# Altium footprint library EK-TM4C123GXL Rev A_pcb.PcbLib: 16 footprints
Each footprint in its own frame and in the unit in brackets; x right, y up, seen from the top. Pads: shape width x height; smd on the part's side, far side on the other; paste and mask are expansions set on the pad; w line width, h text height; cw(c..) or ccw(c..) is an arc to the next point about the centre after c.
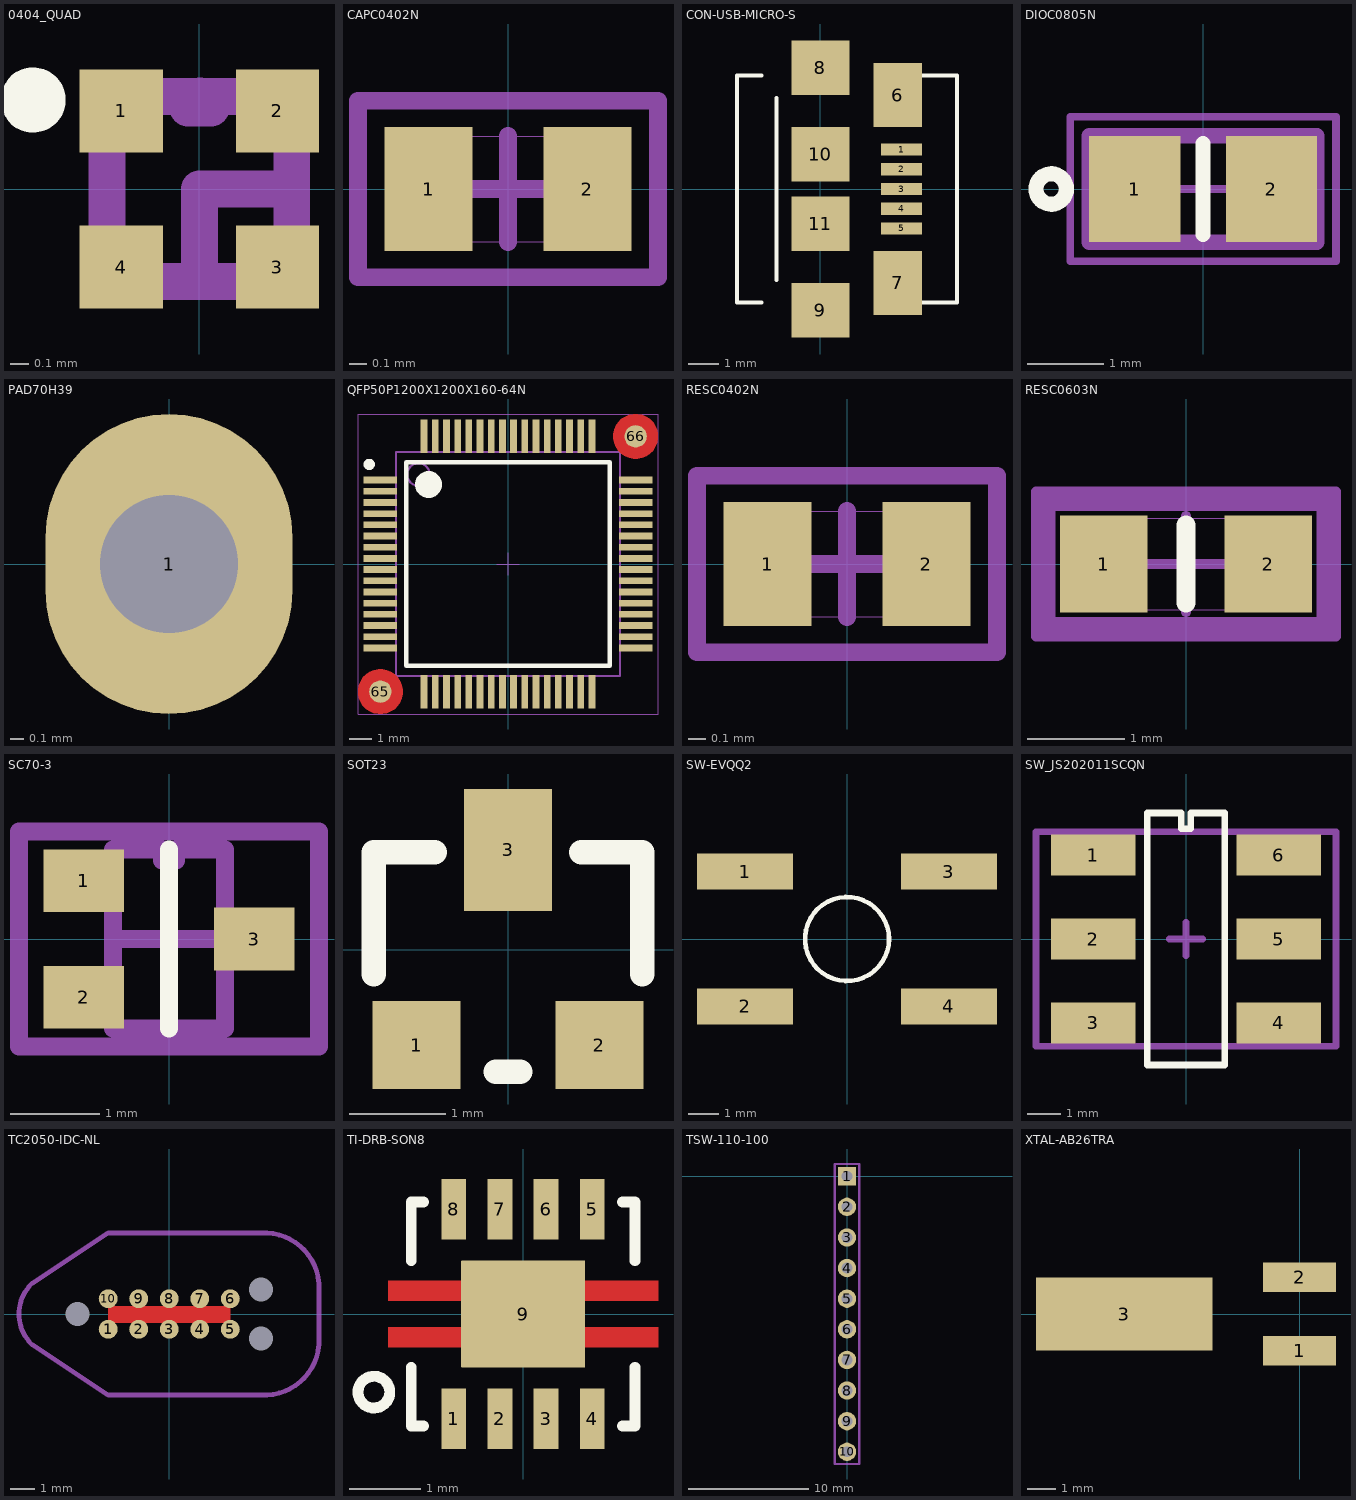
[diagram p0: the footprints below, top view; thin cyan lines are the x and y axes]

## 0404_QUAD [mm]
height 1
pads (4):
  rrect0% 0.45x0.45 smd: 1(-0.423,0.423) 2(0.423,0.423) 3(0.423,-0.423) 4(-0.423,-0.423)
Top Overlay:
  circle w0.2: c-0.9,0.482 r0.076
Mechanical 1:
  lines w0.2: -0.5,-0.5 0.5,-0.5 0.5,0.5 0.062,0.5 0.062,0.437 -0.062,0.437 0.004,0.504 -0.5,0.5 -0.5,-0.5
  text "D1" at 0.406,0.914 h0.64
Mechanical 16:
  lines w0.2: 0,-0.5 0,0 0.5,0 ; -0.5,-0.5 0.5,-0.5 0.5,0.5 -0.5,0.5 -0.5,-0.5

## CAPC0402N [mm]
pads (2):
  rect 0.5x0.7 smd: 1(-0.45,0) 2(0.45,0)
Mechanical 1:
  lines w0.1: -0.85,-0.5 0.85,-0.5 0.85,0.5 -0.85,0.5 -0.85,-0.5
  text "C1" at -0.219,-0.175 h0.38
Mechanical 16:
  lines w0.001: -0.55,-0.3 0.55,-0.3 0.55,0.3 -0.55,0.3 -0.55,-0.3
  lines w0.1: -0.3,0 0.3,0 ; 0,-0.3 0,0.3 ; -0.85,-0.5 0.85,-0.5 0.85,0.5 -0.85,0.5 -0.85,-0.5

## CON-USB-MICRO-S [mm]
pads (11):
  rect 1.35x0.4 smd: 1(2.675,1.3) 2(2.675,0.65) 3(2.675,0) 4(2.675,-0.65) 5(2.675,-1.3)
  rect 1.6x2.1 smd: 6(2.55,3.1) 7(2.55,-3.1)
  rect 1.9x1.8 smd: 8(0,4) 9(0,-4) 10(0,1.15) 11(0,-1.15)
Top Overlay:
  lines w0.127: -1.95,-3.75 -2.75,-3.75 -2.75,3.75 -1.95,3.75 ; -1.45,-3 -1.45,3 ; 2.5,-3.75 4.5,-3.75 4.5,3.75 2.5,3.75

## DIOC0805N [mm]
pads (2):
  rect 1.2x1.4 smd: 1(-0.9,0) 2(0.9,0)
Top Overlay:
  circle w0.2: c-2,0 r0.2
  lines w0.2: 0,-0.6 0,0.6
Mechanical 1:
  lines w0.2: -1.5,-0.7 1.5,-0.7 1.5,0.7 -1.5,0.7 -1.5,-0.7
  text "D4" at -0.456,-0.325 h0.6
Mechanical 16:
  lines w0.001: -1.075,-0.7 1.075,-0.7 1.075,0.7 -1.075,0.7 -1.075,-0.7
  lines w0.1: -0.5,0 0.5,0 ; 0,-0.5 0,0.5 ; -1.75,-0.95 1.75,-0.95 1.75,0.95 -1.75,0.95 -1.75,-0.95

## PAD70H39 [mil]
pads (1):
  oval 70x85 / inner round 70 / far side oval 70x85 hole 39: 1(0,0)

## QFP50P1200X1200X160-64N [mm]
height 1.6
pads (66):
  rect 1.5x0.3 smd: 1(-5.7,3.75) 2(-5.7,3.25) 3(-5.7,2.75) 4(-5.7,2.25) 5(-5.7,1.75) 6(-5.7,1.25) 7(-5.7,0.75) 8(-5.7,0.25) 9(-5.7,-0.25) 10(-5.7,-0.75) 11(-5.7,-1.25) 12(-5.7,-1.75) 13(-5.7,-2.25) 14(-5.7,-2.75) 15(-5.7,-3.25) 16(-5.7,-3.75) 33(5.7,-3.75) 34(5.7,-3.25) 35(5.7,-2.75) 36(5.7,-2.25) 37(5.7,-1.75) 38(5.7,-1.25) 39(5.7,-0.75) 40(5.7,-0.25) 41(5.7,0.25) 42(5.7,0.75) 43(5.7,1.25) 44(5.7,1.75) 45(5.7,2.25) 46(5.7,2.75) 47(5.7,3.25) 48(5.7,3.75)
  rect 0.3x1.5 smd: 17(-3.75,-5.7) 18(-3.25,-5.7) 19(-2.75,-5.7) 20(-2.25,-5.7) 21(-1.75,-5.7) 22(-1.25,-5.7) 23(-0.75,-5.7) 24(-0.25,-5.7) 25(0.25,-5.7) 26(0.75,-5.7) 27(1.25,-5.7) 28(1.75,-5.7) 29(2.25,-5.7) 30(2.75,-5.7) 31(3.25,-5.7) 32(3.75,-5.7) 49(3.75,5.7) 50(3.25,5.7) 51(2.75,5.7) 52(2.25,5.7) 53(1.75,5.7) 54(1.25,5.7) 55(0.75,5.7) 56(0.25,5.7) 57(-0.25,5.7) 58(-0.75,5.7) 59(-1.25,5.7) 60(-1.75,5.7) 61(-2.25,5.7) 62(-2.75,5.7) 63(-3.25,5.7) 64(-3.75,5.7)
  round 1 smd mask+0.5: 65(-5.7,-5.7) 66(5.7,5.7)
Top Layer:
  pour cut-out: -4.7,-5.7 -4.7,-5.602 -4.738,-5.408 -4.814,-5.226 -4.923,-5.063 -5.063,-4.923 -5.226,-4.814 -5.408,-4.738 -5.602,-4.7 -5.7,-4.7 -5.798,-4.7 -5.992,-4.738 -6.174,-4.814 -6.337,-4.923 -6.477,-5.063 -6.586,-5.226 -6.662,-5.408 -6.7,-5.602 -6.7,-5.7 -6.7,-5.798 -6.662,-5.992 -6.586,-6.174 -6.477,-6.337 -6.337,-6.477 -6.174,-6.586 -5.992,-6.662 -5.798,-6.7 -5.7,-6.7 -5.602,-6.7 -5.408,-6.662 -5.226,-6.586 -5.063,-6.477 -4.923,-6.337 -4.814,-6.174 -4.738,-5.992 -4.7,-5.798
  pour cut-out: 6.7,5.7 6.7,5.798 6.662,5.992 6.586,6.174 6.477,6.337 6.337,6.477 6.174,6.586 5.992,6.662 5.798,6.7 5.7,6.7 5.602,6.7 5.408,6.662 5.226,6.586 5.063,6.477 4.923,6.337 4.814,6.174 4.738,5.992 4.7,5.798 4.7,5.7 4.7,5.602 4.738,5.408 4.814,5.226 4.923,5.063 5.063,4.923 5.226,4.814 5.408,4.738 5.602,4.7 5.7,4.7 5.798,4.7 5.992,4.738 6.174,4.814 6.337,4.923 6.477,5.063 6.586,5.226 6.662,5.408 6.7,5.602
Top Overlay:
  circle w0.6: c-3.55,3.55 r0.3
  circle w0.25: c-6.2,4.45 r0.125
  lines w0.2: -4.55,-4.55 4.55,-4.55 4.55,4.55 -4.55,4.55 -4.55,-4.55
Mechanical 1:
  circle w0.1: c-4,4 r0.5
  lines w0.1: -5,-5 5,-5 5,5 -5,5 -5,-5
  text "U1" at -0.451,-0.394 h0.64
Mechanical 16:
  lines w0.001: -5,-5 5,-5 5,5 -5,5 -5,-5
  lines w0.05: -0.5,0 0.5,0 ; 0,-0.5 0,0.5 ; -6.7,-6.7 6.7,-6.7 6.7,6.7 -6.7,6.7 -6.7,-6.7

## RESC0402N [mm]
height 0.35
pads (2):
  rect 0.5x0.7 smd: 1(-0.45,0) 2(0.45,0)
Mechanical 1:
  lines w0.1: -0.85,-0.5 0.85,-0.5 0.85,0.5 -0.85,0.5 -0.85,-0.5
  text "R17" at -0.417,-0.175 h0.38
Mechanical 16:
  lines w0.001: -0.55,-0.3 0.55,-0.3 0.55,0.3 -0.55,0.3 -0.55,-0.3
  lines w0.1: -0.3,0 0.3,0 ; 0,-0.3 0,0.3 ; -0.85,-0.5 0.85,-0.5 0.85,0.5 -0.85,0.5 -0.85,-0.5

## RESC0603N [mm]
height 0.6
pads (2):
  rect 0.9x1 smd: 1(-0.85,0) 2(0.85,0)
Top Overlay:
  lines w0.2: 0,-0.4 0,0.4
Mechanical 1:
  lines w0.2: -1.45,-0.65 1.45,-0.65 1.45,0.65 -1.45,0.65 -1.45,-0.65
  text "R1" at -0.384,-0.344 h0.64
Mechanical 16:
  lines w0.001: -0.85,-0.475 0.85,-0.475 0.85,0.475 -0.85,0.475 -0.85,-0.475
  lines w0.1: -0.5,0 0.5,0 ; 0,-0.5 0,0.5 ; -1.55,-0.75 1.55,-0.75 1.55,0.75 -1.55,0.75 -1.55,-0.75

## SC70-3 [mm]
height 1.27
pads (3):
  rect 0.9x0.7 smd: 1(-0.95,0.65) 2(-0.95,-0.65) 3(0.95,0)
Top Overlay:
  lines w0.2: 0,1 0,0.875 0,1 ; 0,1 0,-1 0,1
Mechanical 1:
  lines w0.2: -0.625,-1 0.625,-1 0.625,1 0.078,1 0.078,0.875 -0.078,0.875 -0.078,1 -0.625,1 -0.625,-1
  text "D2" at 0,0 h0.44
Mechanical 16:
  lines w0.2: -0.5,0 0,0 ; 0,-0.5 0,0 ; 0,0.5 0,0 ; 0.5,0 0,0 ; -1.675,-1.2 1.675,-1.2 1.675,1.2 -1.675,1.2 -1.675,-1.2

## SOT23 [mil]
height 50
pads (3):
  rect 36x36 smd: 1(-37.5,-39) 2(37.5,-39)
  rect 36x50 smd: 3(0,41)
Top Overlay:
  lines w10: -55,-10 -55,40 -30,40 ; -5,-50 5,-50 ; 30,40 55,40 55,-10
Mechanical 1:
  text "Q1" at -67.78,-15.33 h25

## SW-EVQQ2 [mm]
pads (4):
  rect 3.2x1.2 smd: 1(-3.4,2.25) 2(-3.4,-2.25) 3(3.4,2.25) 4(3.4,-2.25)
Top Overlay:
  circle w0.152: c0,0 r1.4
Mechanical 1:
  text "RESET" at -1.575,-0.406 h0.64

## SW_JS202011SCQN [mil]
height 50
pads (6):
  rect 98.5x48 smd: 1(-108.25,98) 2(-108.25,0) 3(-108.25,-98) 4(108.25,-98) 5(108.25,0) 6(108.25,98)
Top Overlay:
  lines w7.87: -45.22,-147 45.22,-147 45.22,147 5.65,147 5.65,128.62 -5.65,128.62 -5.65,147 -45.22,147 -45.22,-147
Mechanical 16:
  lines w7.87: -19.68,0 0,0 ; 0,-19.68 0,0 ; 0,19.68 0,0 ; 19.68,0 0,0 ; -175,-125 175,-125 175,125 -175,125 -175,-125

## TC2050-IDC-NL [mil]
pads (13):
  round 31 smd paste-15.5: 1(-100,-25) 2(-50,-25) 3(0,-25) 4(50,-25) 5(100,-25) 6(100,25) 7(50,25) 8(0,25) 9(-50,25) 10(-100,25)
  round 0 hole 39 unplated: 11(-150,0) 12(150,-40) 13(150,40)
Top Layer:
  pour cut-out: -100,-14 100,-14 100,13 -100,13
Mechanical 16:
  lines w7.87: 150,-132.5 -100,-132.5 -225,-50 cw(c-176.01,0) -224.99,50.01 -100,132.5 150,132.5 ; 150.04,-132.5 ccw(c156.25,-43.75) 245,-49.96 ; 150.04,132.5 cw(c156.25,43.75) 245,49.96 ; 245,-50 245,50

## TI-DRB-SON8 [mm]
pads (13):
  rect 0.35x0.85 smd: 1(-0.975,-1.475) 2(-0.325,-1.475) 3(0.325,-1.475) 4(0.975,-1.475) 5(0.975,1.475) 6(0.325,1.475) 7(-0.325,1.475) 8(-0.975,1.475)
  rrect1% 1.75x1.5 smd paste-0.1: 9(0,0)
  round 0 all layers, no hole: 10(0,0) 11(0,0) 12(0,0) 13(0,0)
Top Layer:
  region: -0.875,0.465 -1.9,0.465 -1.9,0.185 -0.875,0.185
  region: -0.875,-0.185 -1.9,-0.185 -1.9,-0.465 -0.875,-0.465
  region: 1.9,0.465 0.875,0.465 0.875,0.185 1.9,0.185
  region: 1.9,-0.185 0.875,-0.185 0.875,-0.465 1.9,-0.465
Top Overlay:
  circle w0.152: c-2.1,-1.1 r0.224
  lines w0.152: -1.575,-0.75 -1.575,-1.575 -1.4,-1.575 ; -1.575,0.75 -1.575,1.575 -1.4,1.575 ; 1.4,-1.575 1.575,-1.575 1.575,-0.75 ; 1.4,1.575 1.575,1.575 1.575,0.75
Mechanical 1:
  text "U8" at -0.406,0.61 h0.64

## TSW-110-100 [mil]
height 50
pads (10):
  rect 60x60 / inner round 60 / far side rect 60x60 hole 35: 1(0,0)
  round 60 hole 35: 2(0,-100) 3(0,-200) 4(0,-300) 5(0,-400) 6(0,-500) 7(0,-600) 8(0,-700) 9(0,-800) 10(0,-900)
Mechanical 1:
  text "J1" at 36,-68 h25
Mechanical 16:
  lines w7.87: -19.68,0 0,0 ; 0,-19.68 0,0 ; 0,19.68 0,0 ; 19.68,0 0,0 ; -40,-940 40,-940 40,40 -40,40 -40,-940

## XTAL-AB26TRA [mil]
pads (3):
  rect 99x40 smd: 1(0,-50) 2(0,50)
  rect 240x99 smd: 3(-238.5,0)
Mechanical 1:
  text "Y1" at -102.3,-20.94 h25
